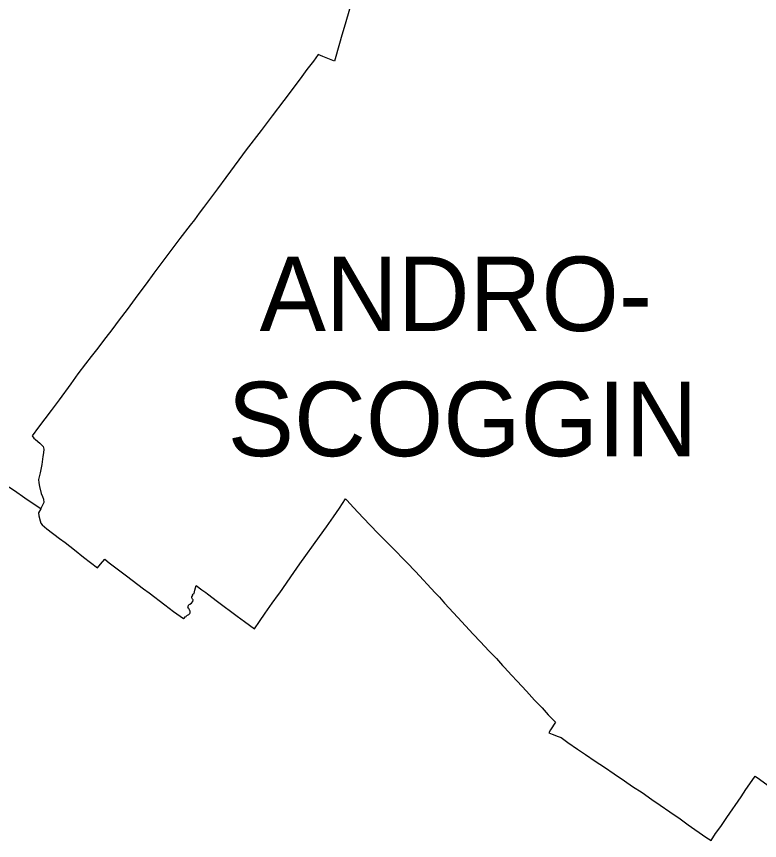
# Model space of a CAD drawing. Extents: x 1104458 to 2179854, y 15641624 to 17244911.
# Drawn here: x 1247959 to 1353437, y 15951707 to 16068731 of the extents above; entities that cross this region are included whole.
import ezdxf

# ---------------------------------------------------------------- set-up
doc = ezdxf.new("R2010")
doc.units = 0
doc.layers.add('ANNOTATION', color=7, linetype='Continuous')
doc.layers.add('CO BORDER', color=7, linetype='Continuous')

msp = doc.modelspace()

# ---------------------------------------------------------------- linework, layer by layer
at = {"layer": 'CO BORDER'}
for points in [[(1296135, 16072837), (1295893, 16072095), (1295368, 16070225), (1294458, 16067145), (1294150, 16066068), (1293808, 16064917), (1293124, 16062400)], [(1293124, 16062400), (1291466, 16063043), (1290800, 16063319), (1290133, 16062404), (1289183, 16061187), (1288241, 16059894), (1285891, 16056820), (1284232, 16054621), (1282682, 16052545), (1280565, 16049789), (1279515, 16048381), (1277665, 16045855), (1276490, 16044264), (1275798, 16043299), (1275365, 16042738)], [(1275365, 16042738), (1274489, 16041606), (1273906, 16040822), (1273206, 16039864), (1272611, 16039080)], [(1272611, 16039080), (1271164, 16037184), (1267463, 16032282), (1266380, 16030776), (1265196, 16029191), (1263671, 16027124), (1262538, 16025635), (1261479, 16024227), (1260654, 16023161), (1259315, 16021409)], [(1259315, 16021409), (1258579, 16020445), (1257737, 16019395), (1256654, 16017961), (1255654, 16016560), (1253995, 16014270), (1252878, 16012777), (1251995, 16011612), (1251103, 16010421), (1250161, 16009188)], [(1250161, 16009188), (1250443, 16008860), (1250648, 16008656), (1251273, 16008122), (1251742, 16007656), (1251820, 16007305), (1251770, 16006763), (1251704, 16006222), (1251554, 16005097), (1251320, 16003902), (1251106, 16002954), (1251125, 16002518), (1251208, 16001976), (1251452, 16000995), (1251629, 16000569), (1251782, 16000182), (1251825, 15999690), (1251481, 15998971), (1251395, 15998814)], [(1251395, 15998814), (1250331, 15999506), (1249126, 16000339), (1247691, 16001347), (1246346, 16002206), (1245596, 16002761), (1245230, 16002249), (1244780, 16001681), (1243816, 16002387), (1243254, 16001602), (1240288, 15997596), (1238197, 15994742), (1237576, 15993935), (1236692, 15992731), (1235730, 15991392), (1235272, 15990792), (1235000, 15990421), (1234618, 15989916), (1234354, 15989506)], [(1271651, 15983216), (1271799, 15983354), (1271918, 15983453), (1272036, 15983541), (1272087, 15983607), (1272138, 15983649), (1272315, 15983745), (1272425, 15983827), (1272518, 15983882), (1272577, 15983958), (1272604, 15984023), (1272613, 15984089), (1272616, 15984224), (1272601, 15984299), (1272560, 15984342), (1272505, 15984483), (1272408, 15984644), (1272350, 15984686), (1272318, 15984729), (1272294, 15984794), (1272313, 15984913), (1272331, 15984962), (1272341, 15985027), (1272375, 15985093), (1272410, 15985178), (1272461, 15985224), (1272562, 15985273), (1272798, 15985428), (1272952, 15985625), (1273011, 15985664), (1273057, 15985890), (1272950, 15985976), (1272902, 15986067), (1272871, 15986186), (1272857, 15986294), (1272952, 15986451), (1272970, 15986507), (1272963, 15986599), (1272998, 15986674), (1273082, 15986730), (1273125, 15986779), (1273183, 15986806), (1273294, 15987272), (1273471, 15987901), (1274265, 15987327), (1274845, 15986934), (1275090, 15986750), (1276501, 15985644), (1279292, 15983574), (1280310, 15982826), (1281738, 15981756), (1282450, 15982826), (1283265, 15983984), (1284259, 15985418), (1285158, 15986632), (1285327, 15986888), (1285771, 15987514), (1286365, 15988407), (1287319, 15989778), (1288201, 15990989), (1290971, 15994900), (1291958, 15996261), (1292945, 15997688), (1293795, 15998892), (1294688, 16000208), (1294851, 16000037)], [(1294851, 16000037), (1295780, 15998997), (1297158, 15997544), (1299275, 15995370), (1301253, 15993389), (1303350, 15991200), (1304601, 15989904), (1307383, 15986902), (1307995, 15986263), (1308730, 15985416), (1310626, 15983382), (1312808, 15981020), (1313838, 15979940), (1315031, 15978644), (1316077, 15977542), (1316961, 15976581)], [(1251395, 15998814), (1251095, 15998233), (1251147, 15997806), (1251320, 15997098), (1251407, 15996786), (1251611, 15996517), (1252286, 15995966), (1254057, 15994611), (1254856, 15994007), (1256197, 15992970), (1257473, 15991966), (1259479, 15990421)], [(1259479, 15990421), (1259893, 15990940), (1260495, 15991674), (1261112, 15991150), (1263577, 15989299), (1265999, 15987459), (1266785, 15986888), (1269037, 15985172), (1270270, 15984240), (1271651, 15983216)], [(1316961, 15976581), (1317238, 15976279), (1318218, 15975186), (1319036, 15974347), (1320351, 15972900), (1321486, 15971630), (1322566, 15970528), (1323416, 15969576), (1324357, 15968661), (1324471, 15968510), (1323786, 15967427), (1323516, 15967020)], [(1323516, 15967020), (1324025, 15966797), (1324861, 15966502), (1325266, 15966328), (1326203, 15965636), (1327585, 15964694), (1328746, 15963923), (1330112, 15962972), (1331429, 15962115), (1332819, 15961157), (1334260, 15960206), (1335420, 15959396), (1336762, 15958539), (1338152, 15957529), (1339320, 15956718), (1340694, 15955777), (1342150, 15954766), (1343293, 15953936), (1345826, 15952194)], [(1345826, 15952194), (1346552, 15951707), (1347202, 15952688), (1347928, 15953708), (1348808, 15954994), (1350833, 15957908), (1351509, 15958931), (1352405, 15960224), (1352799, 15960824), (1353425, 15960414), (1354675, 15959542), (1355827, 15958721)]]:
    msp.add_lwpolyline(points, dxfattribs=at)

# ---------------------------------------------------------------- texts
at = {"layer": 'ANNOTATION'}
for s, p in [('ANDRO-', (1282468, 16024067)), ('SCOGGIN', (1277937, 16006289))]:
    msp.add_text(s, height=10560.2, dxfattribs=at).set_placement(p)

doc.saveas('drawing.dxf')
